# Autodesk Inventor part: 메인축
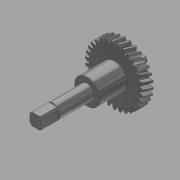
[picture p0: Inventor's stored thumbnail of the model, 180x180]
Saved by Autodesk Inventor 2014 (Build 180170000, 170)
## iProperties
Created: 2017-11
Part Number: 메인축
Material: 강철, 탄소
Document SubType Name: Modeling
Designer: mduedu
Categories: <?xml version="1.0" encoding="UTF-16"?> <MemberInstance><Categories><FamilyTemplate><FamilyTemplateParameter ValueType="xs:double" Id="1" ObjectReferenceKey="da
Density: 7.87 g/cm^3
Mass: 607.365 g
Surface Area: 183.17 cm^2
Volume: 77.1747 cm^3
Appearance: 반광택
CustomPartVersion: 1
Author: mduedu
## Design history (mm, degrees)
sketch "Sketch1"
  geometry: C1 r 34.094 at (0, 0)
  constraints: 1 centre point
  dimensions: "d0" = 68.18712 diameter of C1 (= da_da)
extrude "Extrusion1" new body sketch "Sketch1" distance "d1" = 12 (= da_b); taper "d2" = 0 deg
workplane "Work Plane2"
sketch "Sketch2"
  geometry: C1 r 34.094 at (0, 0) reference; C2 r 32.094 at (0, 0)
  constraints: 1 centre point, 1 coincident
  dimensions: "d3" = 64.18712 diameter of C2 (= da_dw)
feature "피치 지름" sketch "Sketch2" dims "d4" = 10, "d5" = 0
workplane "Work Plane8"
workplane "Work Plane9"
feature "스퍼 기어" dims "da_b" = 12, "da_d" = 64.18712, "da_aw" = 54.86964, "da_da" = 68.18712, "da_df" = 59.18712, "da_dw" = 64.18712, angle "da_beta" = 15 deg, "da_lefttooth" = 0, "da_righttooth" = 10
sketch "스케치3"
  geometry: C1 r 15 at (0, 0); 1 further point
  constraints: 1 centre point, 1 coincident
  dimensions: "d49" = 30 diameter of C1
extrude "돌출2" join sketch "스케치3" distance "d50" = 32; taper "d51" = 0 deg
sketch "스케치4"
  geometry: C1 r 8.5 at (0, 0); 1 further point
  constraints: 1 centre point, 1 coincident
  dimensions: "d52" = 17 diameter of C1
extrude "돌출3" join sketch "스케치4" distance "d53" = 60; taper "d54" = 0 deg
sketch "스케치5"
  geometry: C1 r 7.5 at (0, 0); 1 further point
  constraints: 1 centre point, 1 coincident
  dimensions: "d55" = 15 diameter of C1
extrude "돌출4" join sketch "스케치5" distance "d56" = 16; taper "d57" = 0 deg
sketch "스케치6"
  geometry: C1 r 4 at (0, 0); 1 further point
  constraints: 1 centre point, 1 coincident
  dimensions: "d58" = 8 diameter of C1
extrude "돌출5" join sketch "스케치6" distance "d59" = 7; taper "d60" = 0 deg
chamfer "모따기1" distance "d61" = 0.5; stored, may be unused: second distance "d62" = 2, angle "d63" = 45 deg
fillet "모깎기1" dims "d64" = 0.5
sketch "스케치7"
  geometry: L1 (-7, -7)-(7, -7); L2 (7, -7)-(7, 7); L3 (7, 7)-(-7, 7); L4 (-7, 7)-(-7, -7); L5 (-7, -7)-(7, 7); L6 (7, -7)-(-7, 7); L7 (-10, -10)-(10, -10); L8 (10, -10)-(10, 10); L9 (10, 10)-(-10, 10); L10 (-10, 10)-(-10, -10); L11 (-10, -10)-(10, 10); L12 (10, -10)-(-10, 10); 1 further point
  constraints: 24 end point, 4 midpoint, 4 parallel, 2 horizontal, 2 perpendicular
  dimensions: "d65" = 14 distance of L3.end L2.end; "d66" = 14 distance of L2.end L1.end; "d67" = 20 distance of L9.end L8.end; "d68" = 20 distance of L8.end L7.end
extrude "돌출6" cut sketch "스케치7" distance "d69" = 20; taper "d70" = 0 deg
body "Solid1"
body "Srf1"
other parameters: "d16" = 54.86964 (= da_aw), "d17" = 0, "d34" = 1.01342 (computed from da_z), "d39" = 0, "d41" = 0, "d43" = 54.86964 (= da_aw), "d46" = 54.86964 (= da_aw), "d47" = 0, "d48" = 0
